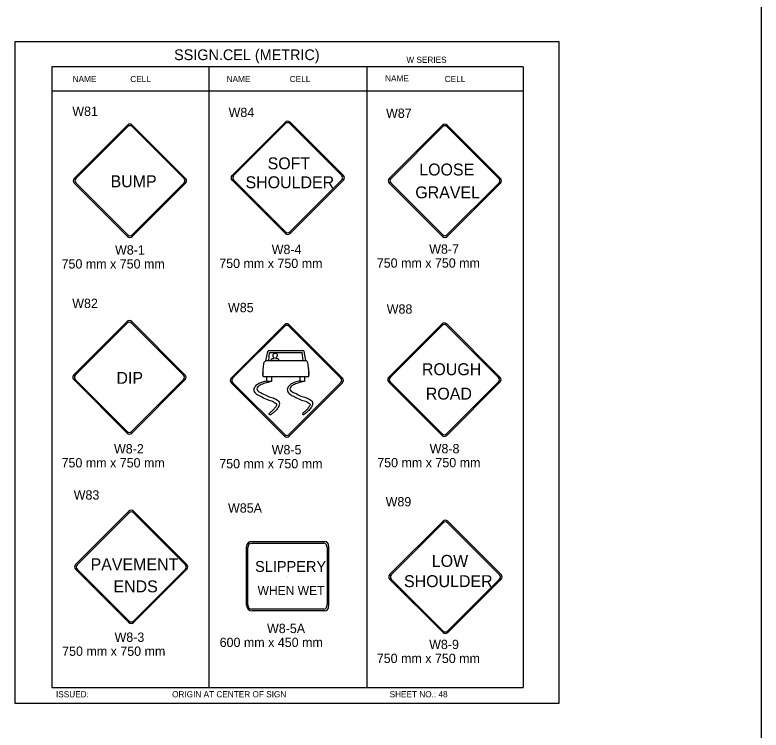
# Model space of a CAD drawing. Extents: x -12 to 6962, y -3756 to 679.
# Drawn here: x 2373.2 to 2613.4, y -13.7 to 216.7 of the extents above; entities that cross this region are included whole.
import ezdxf

# ---------------------------------------------------------------- set-up
doc = ezdxf.new("R2010")
doc.units = 0
for name, color, linetype in [('Level 1', 7, 'Continuous'), ('Level 2', 7, 'Continuous'), ('Level 3', 7, 'Continuous'), ('Level 62', 7, 'Continuous')]:
    doc.layers.add(name, color=color, linetype=linetype)

msp = doc.modelspace()

# ---------------------------------------------------------------- linework, layer by layer
at = {"layer": 'Level 1'}
for p, q in [((2536.79, 200), (2385.04, 200)), ((2385.04, 200), (2385.04, 0)), ((2435.62, 200), (2435.62, 0)), ((2486.49, 200), (2486.49, 0)), ((2536.79, 200), (2536.79, 0)), ((2536.79, 192.08), (2385.04, 192.08)), ((2392.24, 164.01), (2409.43, 181.21)), ((2392.74, 163.95), (2409.49, 180.71)), ((2410.86, 180.71), (2427.62, 163.95)), ((2410.93, 181.21), (2428.12, 164.01)), ((2443.06, 164.96), (2460.25, 182.15)), ((2443.55, 164.9), (2460.31, 181.65)), ((2461.68, 181.65), (2478.44, 164.9)), ((2461.74, 182.15), (2478.94, 164.96)), ((2493.65, 164), (2510.85, 181.19)), ((2494.15, 163.93), (2510.91, 180.69)), ((2512.28, 180.69), (2529.04, 163.93)), ((2512.34, 181.19), (2529.53, 164)), ((2460.25, 146.27), (2443.06, 163.47)), ((2460.31, 146.77), (2443.55, 163.53)), ((2460.95, 164.14), (2460.95, 164.14)), ((2478.44, 163.53), (2461.68, 146.77)), ((2478.94, 163.46), (2461.74, 146.27)), ((2409.43, 145.33), (2392.24, 162.52)), ((2409.49, 145.83), (2392.74, 162.58)), ((2410.14, 163.19), (2410.14, 163.19)), ((2427.62, 162.58), (2410.86, 145.83)), ((2428.12, 162.52), (2410.93, 145.33)), ((2510.85, 145.31), (2493.65, 162.5)), ((2510.91, 145.81), (2494.15, 162.56)), ((2511.55, 163.18), (2511.55, 163.18)), ((2529.04, 162.56), (2512.28, 145.81)), ((2529.53, 162.5), (2512.34, 145.31)), ((2392.09, 100.7), (2409.28, 117.89)), ((2410.78, 117.89), (2427.97, 100.69)), ((2392.59, 100.63), (2409.34, 117.39)), ((2410.71, 117.39), (2427.47, 100.63)), ((2442.76, 99.71), (2459.95, 116.9)), ((2443.26, 99.64), (2460.02, 116.4)), ((2461.39, 116.4), (2478.14, 99.64)), ((2461.45, 116.9), (2478.64, 99.71)), ((2493.49, 99.93), (2510.68, 117.13)), ((2493.99, 99.87), (2510.75, 116.63)), ((2512.12, 116.63), (2528.87, 99.87)), ((2512.18, 117.13), (2529.37, 99.93)), ((2453.99, 105.31), (2454.55, 108.26)), ((2454.93, 108.57), (2465.9, 108.57)), ((2466.83, 105.33), (2466.28, 108.26)), ((2454.92, 105.33), (2455.12, 107.93)), ((2455.12, 107.93), (2465.68, 107.93)), ((2465.93, 105.33), (2465.68, 107.93)), ((2453.99, 105.33), (2466.83, 105.33)), ((2453.11, 100.24), (2453.11, 102.61)), ((2467.74, 100.24), (2467.74, 102.64)), ((2409.28, 82.01), (2392.09, 99.2)), ((2409.34, 82.51), (2392.59, 99.26)), ((2409.99, 99.87), (2409.99, 99.87)), ((2427.47, 99.26), (2410.72, 82.51)), ((2427.97, 99.2), (2410.78, 82.01)), ((2453.11, 100.24), (2467.74, 100.24)), ((2460.66, 98.88), (2460.66, 98.88)), ((2511.39, 99.11), (2511.39, 99.11)), ((2459.95, 81.02), (2442.76, 98.21)), ((2460.02, 81.52), (2443.26, 98.27)), ((2478.14, 98.27), (2461.39, 81.52)), ((2478.64, 98.21), (2461.45, 81.02)), ((2510.68, 81.24), (2493.49, 98.44)), ((2510.75, 81.74), (2493.99, 98.5)), ((2528.87, 98.5), (2512.12, 81.74)), ((2529.37, 98.44), (2512.18, 81.24)), ((2454.86, 88.19), (2455.49, 87.84)), ((2465.7, 88.25), (2466.11, 87.77)), ((2392.66, 39.63), (2409.85, 56.82)), ((2393.16, 39.56), (2409.92, 56.32)), ((2411.29, 56.32), (2428.04, 39.56)), ((2411.35, 56.82), (2428.54, 39.63)), ((2493.82, 36.41), (2511.02, 53.6)), ((2494.32, 36.35), (2511.08, 53.1)), ((2512.45, 53.1), (2529.2, 36.35)), ((2512.51, 53.6), (2529.7, 36.41)), ((2449.32, 46.53), (2472.6, 46.53)), ((2449.45, 47.09), (2472.95, 47.09)), ((2447.75, 26.51), (2447.75, 45.39)), ((2448.2, 26.64), (2448.2, 45.16)), ((2473.72, 45.16), (2473.72, 26.64)), ((2474.17, 45.6), (2474.17, 26.21)), ((2410.56, 38.81), (2410.56, 38.81)), ((2409.85, 20.94), (2392.66, 38.13)), ((2409.92, 21.44), (2393.16, 38.19)), ((2428.04, 38.19), (2411.29, 21.44)), ((2428.54, 38.13), (2411.35, 20.94)), ((2460.82, 35.71), (2460.82, 35.71)), ((2511.02, 17.72), (2493.82, 34.91)), ((2511.08, 18.22), (2494.32, 34.98)), ((2511.72, 35.59), (2511.72, 35.59)), ((2529.2, 34.98), (2512.45, 18.22)), ((2529.7, 34.91), (2512.51, 17.72)), ((2472.6, 25.27), (2449.31, 25.27)), ((2472.95, 24.71), (2449.55, 24.71)), ((2385.04, 0), (2536.79, 0))]:
    msp.add_line(p, q, dxfattribs=at)
for points in [[(2454.26, 98.64), (2454.26, 100.21), (2455.76, 100.21), (2455.76, 98.64)], [(2464.95, 98.64), (2464.95, 100.21), (2466.44, 100.21), (2466.44, 98.64)]]:
    msp.add_lwpolyline(points, close=True, dxfattribs=at)
for centre, radius, start, end in [((2410.18, 180.46), 1.06, 45, 135), ((2410.18, 180.02), 0.969, 45, 135), ((2461, 181.4), 1.06, 45, 135), ((2461, 180.97), 0.969, 45, 135), ((2511.59, 180.44), 1.06, 45, 135), ((2511.59, 180.01), 0.969, 45, 135), ((2392.99, 163.27), 1.06, 135, 225), ((2393.42, 163.27), 0.969, 135, 225), ((2426.94, 163.27), 0.969, 315, 45), ((2427.37, 163.27), 1.06, 315, 45), ((2443.8, 164.21), 1.06, 135, 225), ((2444.24, 164.21), 0.969, 135, 225), ((2477.75, 164.21), 0.969, 315, 45), ((2478.19, 164.21), 1.06, 315, 45), ((2494.4, 163.25), 1.06, 135, 225), ((2494.84, 163.25), 0.969, 135, 225), ((2528.35, 163.25), 0.969, 315, 45), ((2528.79, 163.25), 1.06, 315, 45), ((2461, 147.46), 0.969, 225, 315), ((2410.18, 146.07), 1.06, 225, 315), ((2410.18, 146.51), 0.969, 225, 315), ((2461, 147.02), 1.06, 225, 315), ((2511.59, 146.06), 1.06, 225, 315), ((2511.59, 146.49), 0.969, 225, 315), ((2410.03, 117.14), 1.06, 45, 135), ((2410.03, 116.7), 0.969, 45, 135), ((2460.7, 116.15), 1.06, 45, 135), ((2460.7, 115.71), 0.969, 45, 135), ((2511.43, 116.38), 1.06, 45, 135), ((2511.43, 115.94), 0.969, 45, 135), ((2454.93, 108.2), 0.383, 90.1223, 169.2756), ((2454.93, 108.19), 0.383, 90, 169.2714), ((2465.9, 108.19), 0.383, 10.7244, 90), ((2392.84, 99.95), 1.06, 135, 225), ((2393.27, 99.95), 0.969, 135, 225), ((2426.79, 99.95), 0.969, 315, 45), ((2427.22, 99.95), 1.06, 315, 45), ((2443.51, 98.96), 1.06, 135, 225), ((2443.94, 98.96), 0.969, 135, 225), ((2477.46, 98.96), 0.969, 315, 45), ((2477.89, 98.96), 1.06, 315, 45), ((2494.24, 99.19), 1.06, 135, 225), ((2494.67, 99.19), 0.969, 135, 225), ((2528.19, 99.18), 0.969, 315, 45), ((2528.62, 99.18), 1.06, 315, 45), ((2410.03, 82.75), 1.06, 225, 315), ((2410.03, 83.19), 0.969, 225, 315), ((2511.43, 82.43), 0.969, 225, 315), ((2460.7, 81.77), 1.06, 225, 315), ((2460.7, 82.2), 0.969, 225, 315), ((2511.43, 81.99), 1.06, 225, 315), ((2410.6, 56.07), 1.06, 45, 135), ((2410.6, 55.64), 0.969, 45, 135), ((2511.76, 52.85), 1.06, 45, 135), ((2511.76, 52.42), 0.969, 45, 135), ((2449.45, 45.39), 1.7, 90, 180), ((2393.41, 38.88), 1.06, 135, 225), ((2393.84, 38.88), 0.969, 135, 225), ((2427.36, 38.88), 0.969, 315, 45), ((2427.79, 38.88), 1.06, 315, 45), ((2494.57, 35.66), 1.06, 135, 225), ((2495.01, 35.66), 0.969, 135, 225), ((2528.52, 35.66), 0.969, 315, 45), ((2528.96, 35.66), 1.06, 315, 45), ((2449.55, 26.51), 1.8, 180, 270), ((2410.6, 21.69), 1.06, 225, 315), ((2410.6, 22.12), 0.969, 225, 315), ((2511.76, 18.47), 1.06, 225, 315), ((2511.76, 18.9), 0.969, 225, 315)]:
    msp.add_arc(centre, radius, start, end, dxfattribs=at)
for centre, major_axis, start_param, end_param in [((2449.32, 45.16), (0, 1.37), 0, 1.570796), ((2472.6, 45.16), (0, 1.37), 4.712389, 6.283185), ((2472.95, 45.6), (0, 1.49), 4.712389, 6.283185), ((2449.32, 26.64), (0, -1.37), 4.712389, 6.283185), ((2472.6, 26.64), (0, -1.37), 0, 1.570796), ((2472.95, 26.21), (0, -1.49), 0, 1.570796)]:
    msp.add_ellipse(centre, major_axis=major_axis, ratio=0.817773, start_param=start_param, end_param=end_param, dxfattribs=at)
for points in [[(2455.68, 105.34), (2455.69, 105.61), (2455.82, 105.87), (2456.11, 105.98), (2456.44, 105.98), (2456.6, 105.99), (2456.59, 106.1), (2456.52, 106.31), (2456.35, 106.5), (2456.27, 106.71)], [(2456.86, 107.71), (2456.82, 107.71), (2456.72, 107.66), (2456.56, 107.58), (2456.44, 107.47), (2456.31, 107.29), (2456.21, 107.09), (2456.23, 106.87), (2456.27, 106.71)], [(2456.82, 107.7), (2456.93, 107.73), (2457.06, 107.74), (2457.18, 107.73), (2457.27, 107.72), (2457.32, 107.7)], [(2457.32, 107.68), (2457.35, 107.68), (2457.49, 107.49), (2457.61, 107.2), (2457.57, 106.95), (2457.51, 106.68), (2457.41, 106.47), (2457.3, 106.33), (2457.16, 106.22), (2457.11, 106.09), (2457.19, 106.04), (2457.46, 106.02), (2457.7, 105.98), (2457.99, 105.82), (2458.02, 105.67), (2458.07, 105.47), (2458.05, 105.34)], [(2453.11, 102.61), (2453.21, 103.64), (2453.35, 104.6), (2453.6, 105.06), (2453.99, 105.31)], [(2467.72, 102.64), (2467.62, 103.67), (2467.47, 104.62), (2467.23, 105.09), (2466.83, 105.33)], [(2453.09, 100.46), (2453.01, 100.63), (2452.94, 100.9), (2453.04, 101.12), (2452.96, 101.39), (2452.94, 101.58), (2453.04, 101.71)], [(2467.74, 100.46), (2467.82, 100.63), (2467.89, 100.9), (2467.79, 101.12), (2467.87, 101.39), (2467.89, 101.58), (2467.79, 101.71)], [(2454.28, 98.77), (2453.23, 98.5), (2451.55, 97.85), (2450.55, 97.04), (2450.06, 95.99), (2450.61, 94.8), (2452.23, 93.86), (2454.12, 92.89), (2455.8, 92.38), (2457.09, 91.66), (2457.35, 91.36), (2457.35, 90.95), (2457.12, 90.46), (2456.38, 89.53), (2455.6, 88.79), (2454.86, 88.19)], [(2455.77, 98.59), (2453.65, 98.04), (2452.12, 97.45), (2451.34, 96.83), (2451.07, 96.25), (2451.38, 95.59), (2452.78, 94.78), (2454.59, 93.85), (2456.28, 93.33), (2457.77, 92.51), (2458.29, 91.9), (2458.29, 91.04), (2457.95, 90.32), (2457.13, 89.28), (2456.28, 88.48), (2455.49, 87.84)], [(2464.94, 98.85), (2464.15, 98.64), (2462.43, 97.98), (2461.39, 97.14), (2460.85, 95.99), (2461.46, 94.69), (2463.12, 93.73), (2465.02, 92.75), (2466.7, 92.24), (2467.96, 91.55), (2468.17, 91.31), (2468.17, 90.99), (2467.95, 90.54), (2467.24, 89.63), (2466.47, 88.9), (2465.73, 88.32)], [(2466.42, 98.63), (2464.3, 98.08), (2462.77, 97.49), (2462, 96.86), (2461.72, 96.29), (2462.03, 95.63), (2463.43, 94.82), (2465.24, 93.89), (2466.93, 93.37), (2468.42, 92.55), (2468.94, 91.94), (2468.94, 91.08), (2468.6, 90.35), (2467.78, 89.31), (2466.93, 88.52), (2466.14, 87.88)]]:
    msp.add_spline(points, degree=3, dxfattribs=at)
at = {"layer": 'Level 3'}
msp.add_line((2613.41, 661.66), (2613.41, -1225.34), dxfattribs=at)
at = {"layer": 'Level 62'}
msp.add_lwpolyline([(2373.16, -5.05), (2548.42, -5.05), (2548.42, 208.05), (2373.16, 208.05)], close=True, dxfattribs=at)

# ---------------------------------------------------------------- texts
at = {"layer": 'Level 1'}
for s, height, p in [('SOFT', 3.842, (2454.52, 166.94)), ('LOOSE', 3.842, (2503.34, 164.96)), ('BUMP', 3.842, (2403.95, 161.17)), ('SHOULDER', 3.842, (2447.41, 160.85)), ('GRAVEL', 3.842, (2502.07, 157.6)), ('ROUGH', 3.842, (2504.19, 100.64)), ('DIP', 3.842, (2405.84, 97.85)), ('ROAD', 3.842, (2505.46, 92.77)), ('PAVEMENT', 3.842, (2397.52, 37.8)), ('LOW', 3.842, (2507.39, 38.9)), ('SLIPPERY', 3.5, (2450.48, 37.27)), ('SHOULDER', 3.842, (2498.43, 32.37)), ('ENDS', 3.842, (2404.88, 30.69)), ('WHEN WET', 2.9, (2451.29, 29.83))]:
    msp.add_text(s, height=height, dxfattribs=at).set_placement(p)
at = {"layer": 'Level 2'}
for s, p in [('W81', (2391.64, 184.13)), ('W84', (2441.96, 183.79)), ('W87', (2492.66, 183.51)), ('W82', (2391.61, 122.27)), ('W85', (2441.77, 120.93)), ('W88', (2492.88, 120.45)), ('W83', (2392.09, 60.56)), ('W89', (2492.53, 58.38)), ('W85A', (2441.77, 56.36))]:
    msp.add_text(s, height=3, dxfattribs=at).set_placement(p)
at = {"layer": 'Level 3'}
for s, height, p in [('SSIGN.CEL (METRIC)', 3.4642, (2424.42, 202.11)), ('W SERIES', 1.979, (2499.21, 201.24)), ('NAME', 1.98, (2391.74, 195.04)), ('CELL', 1.98, (2410.3, 195.04)), ('NAME', 1.98, (2441.32, 195.04)), ('CELL', 1.98, (2461.65, 195.04)), ('NAME', 1.98, (2492.35, 195.25)), ('CELL', 1.98, (2511.56, 195.04)), ('W8-1', 3, (2405.4, 139.48)), ('W8-4', 3, (2455.84, 139.65)), ('W8-7', 3, (2506.55, 139.76)), ('750 mm x 750 mm', 3, (2388.18, 134.98)), ('750 mm x 750 mm', 3, (2438.96, 135.15)), ('750 mm x 750 mm', 3, (2489.67, 135.26)), ('W8-2', 3, (2405.06, 75.42)), ('W8-5', 3, (2455.84, 75.13)), ('W8-8', 3, (2506.71, 75.47)), ('750 mm x 750 mm', 3, (2388.18, 70.92)), ('750 mm x 750 mm', 3, (2438.96, 70.63)), ('750 mm x 750 mm', 3, (2489.83, 70.97)), ('W8-5A', 3, (2454.33, 17.57)), ('W8-3', 3, (2405.24, 14.74)), ('600 mm x 450 mm', 3, (2439.08, 13.07)), ('W8-9', 3, (2506.54, 12.42)), ('750 mm x 750 mm', 3, (2388.37, 10.24)), ('750 mm x 750 mm', 3, (2489.67, 7.92)), ('ISSUED:', 1.98, (2386.38, -3.12)), ('ORIGIN AT CENTER OF SIGN', 1.9795, (2423.76, -3.12)), ('SHEET NO.: 48', 1.9795, (2493.8, -3.12))]:
    msp.add_text(s, height=height, dxfattribs=at).set_placement(p)

doc.saveas('drawing.dxf')
